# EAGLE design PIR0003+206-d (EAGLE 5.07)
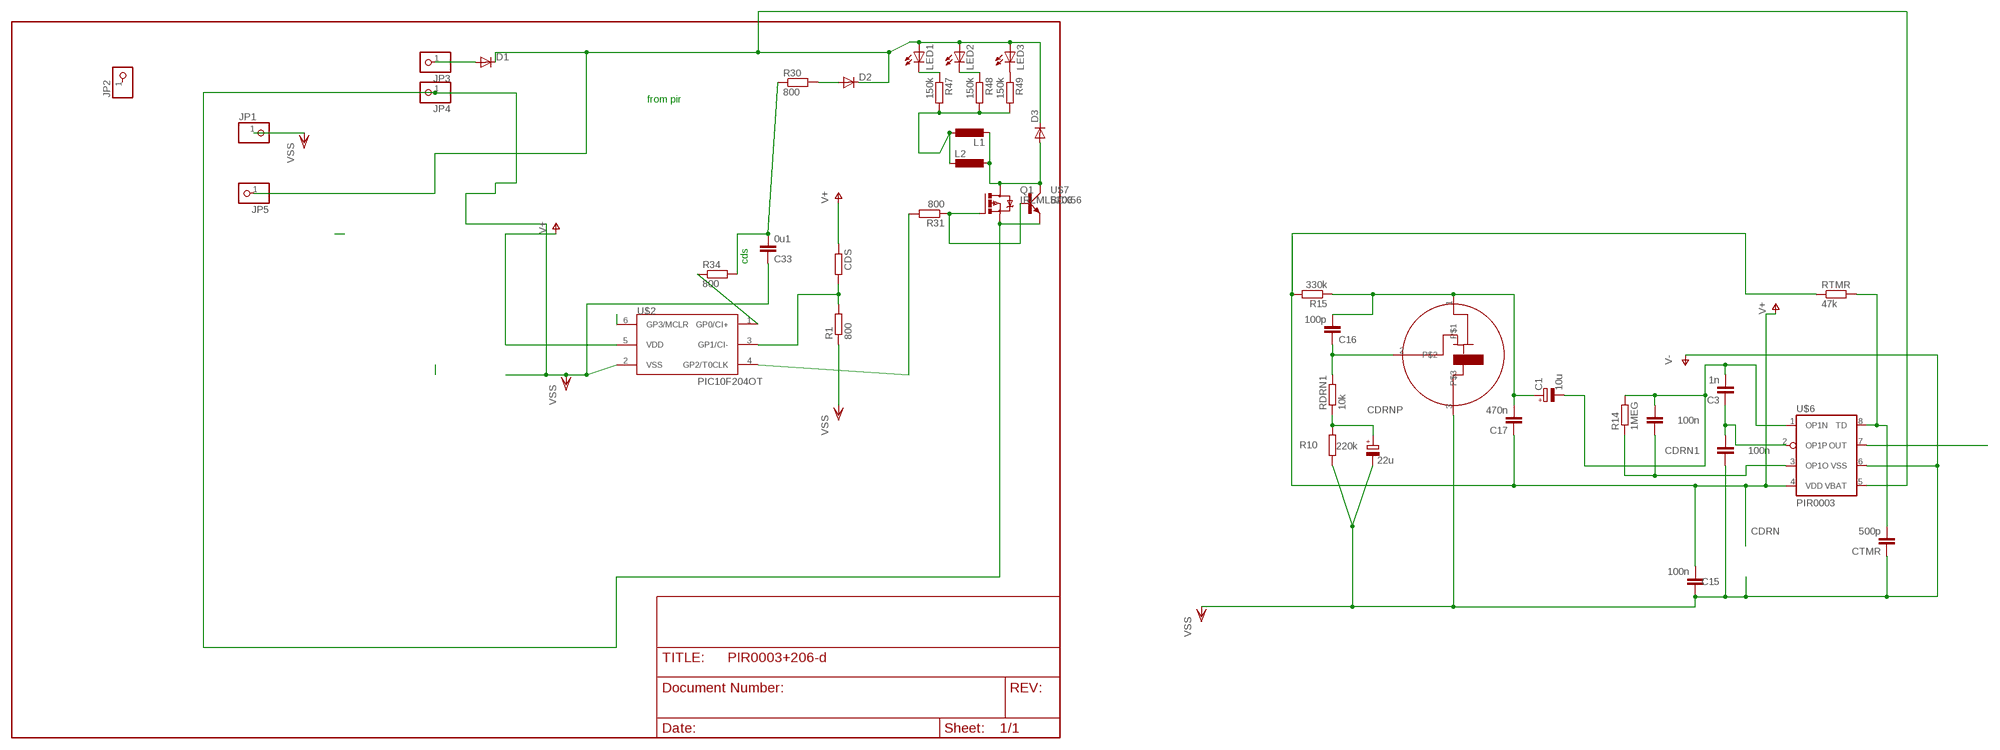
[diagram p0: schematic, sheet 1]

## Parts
C1  10u  CPOL-EUSMCA  [SMC_A]
C3  1n  C-EUC0805  [C0805]
C15  100n  C-EUC1206  [C1206]
C16  100p  C-EUC0805  [C0805]
C17  470n  C-EUC0805  [C0805]
C33  0u1  C-EUC0805  [C0805]
CDRN  100n  C-EUC0805  [C0805]
CDRN1  100n  C-EUC0805  [C0805]
CDRNP  22u  CPOL-EUSMCB  [SMC_B]
CDS  R-EU_0207/5V  [0207/5V]
CTMR  500p  C-EUC0805  [C0805]
D1  DIODE-MINIMELF  [MINIMELF]
D2  DIODE-MINIMELF  [MINIMELF]
D3  DIODE-SMC  [SMC]
JP1  PINHD-1X1  [1X01]
JP2  PINHD-1X1  [1X01]
JP3  PINHD-1X1  [1X01]
JP4  PINHD-1X1  [1X01]
JP5  PINHD-1X1  [1X01]
L1  L-EUL5650M  [L5650M]
L2  L-EU0207/7  [0207/7@1]
LED1  LED1W1MM6  [1W1MM6]
LED2  LED1W1MM6  [1W1MM6]
LED3  LED1W1MM6  [1W1MM6]
PIR1  RE200B  [R200B]
Q1  IRLML5203  [MICRO3]
R1  800  R-EU_R0805  [R0805]
R10  220k  R-EU_R0805  [R0805]
R14  1MEG  R-EU_R0805  [R0805]
R15  330k  R-EU_R0805  [R0805]
R30  800  R-EU_R1206  [R1206]
R31  800  R-EU_R0805  [R0805]
R34  800  R-EU_R1206  [R1206]
R47  150k  R-EU_R1206  [R1206]
R48  150k  R-EU_R1206  [R1206]
R49  150k  R-EU_R1206  [R1206]
RDRN1  10k  R-EU_R0805  [R0805]
RTMR  47k  R-EU_R0805  [R0805]
U$2  PIC10F204OT  [SOT23-6]
U$6  PIR0003  [SO08]
U$7  BCX56  [SOT223]

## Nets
LED-: L1.1 L2.2 R47.2 R48.2 R49.2
N$1: CDS.2 R1.2 U$2.3(GP1/CI-)
N$6: D2.A R30.2
N$8: C1.+ C16.2 C17.2 PIR1.1 R15.1
N$9: CDRNP.+ R10.2 RDRN1.1
N$10: Q1.1(G) R31.1 U$7.1(B)
N$11: D1.A JP3.1
N$14: R31.2 U$2.4(GP2/T0CLK)
N$15: C1.- C3.2 CDRN1.2 R14.2 U$6.1(OP1N)
N$17: C33.2 R30.1 R34.2
N$18: C3.1 CDRN.2 U$6.2(OP1P)
N$20: CDRN1.1 R14.1 U$6.3(OP1O)
N$21: CTMR.2 RTMR.2 U$6.8(TD)
N$23: C16.1 PIR1.2 RDRN1.2
N$26: D3.A L1.2 L2.1 Q1.3(D) U$7.2(C)
N$29: R34.1 U$2.1(GP0/CI+)
N$38: LED1.C R47.1
N$54: LED2.C R48.1
N$55: LED3.C R49.1
OUT: U$2.6(GP3/MCLR) U$6.7(OUT)
V5: D1.C D2.C D3.C JP5.1 LED1.A LED2.A LED3.A U$6.5(VBAT)
V+: C15.2 C17.1 CDS.1 R15.2 RTMR.1 U$2.5(VDD) U$6.4(VDD)
VSS: C15.1 C33.1 CDRN.1 CDRNP.- CTMR.1 JP1.1 JP4.1 PIR1.3 Q1.2(S) R1.1 R10.1 U$2.2(VSS) U$6.6(VSS) U$7.3(E) ; supply symbol labelled V-
Unconnected: JP2.1

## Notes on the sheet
- from pir
- cds

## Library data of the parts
C1 CDRNP = rcl:CPOL-EU: POLARIZED CAPACITOR, European symbol
C3 C15-C17 C33 CDRN CDRN1 CTMR = rcl:C-EU: CAPACITOR, European symbol
CDS = rcl(2):R-EU_: RESISTOR, European symbol
D1-D3 = diode:DIODE-: DIODE
JP1-JP5 = pinhead:PINHD-1X1: PIN HEADER
L1 = rcl-2:L-EU: INDUCTOR, European symbol
L2 = rcl:L-EU: INDUCTOR, European symbol
LED1-LED3 = led:LED: LED
PIR1 = photo-elements:RE200B
Q1 = transistor-power:IRLML5203: HEXFET P-Channel Power MOSFET
R1 R10 R14 R15 R30 R31 R34 R47-R49 RDRN1 RTMR = rcl:R-EU_: RESISTOR, European symbol
U$2 = microchip-3:PIC10F2*: uPC nW 0,25/0,5k Program Flash memory Comparator
U$6 = linear:PIR0003
U$7 = transistor-power:BCX56

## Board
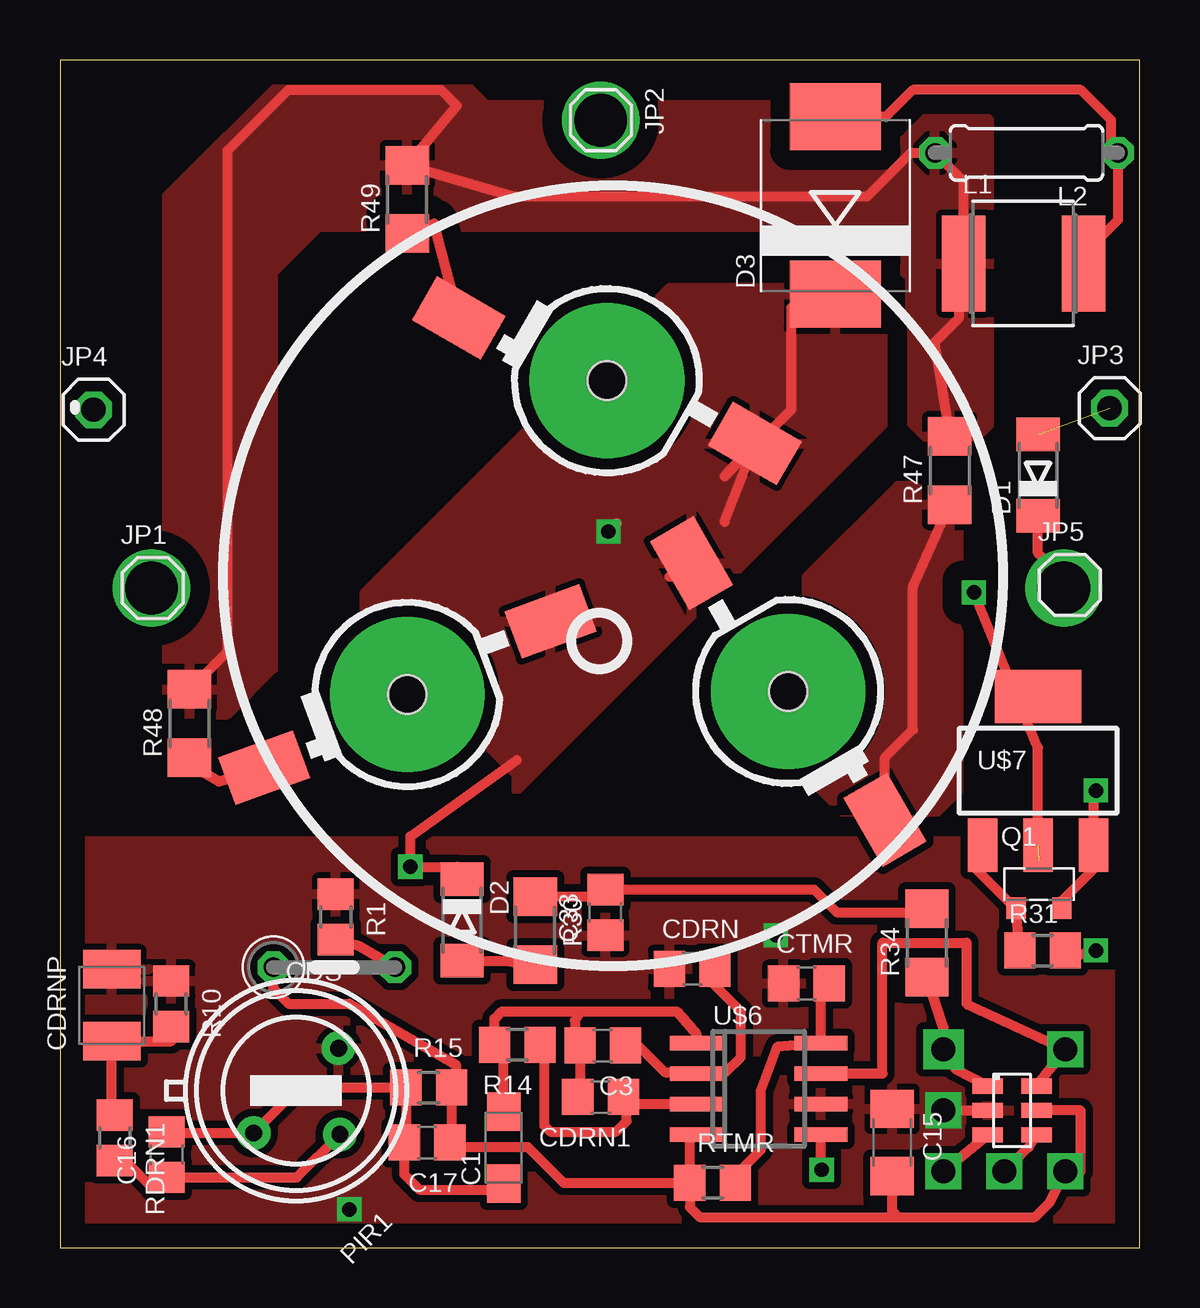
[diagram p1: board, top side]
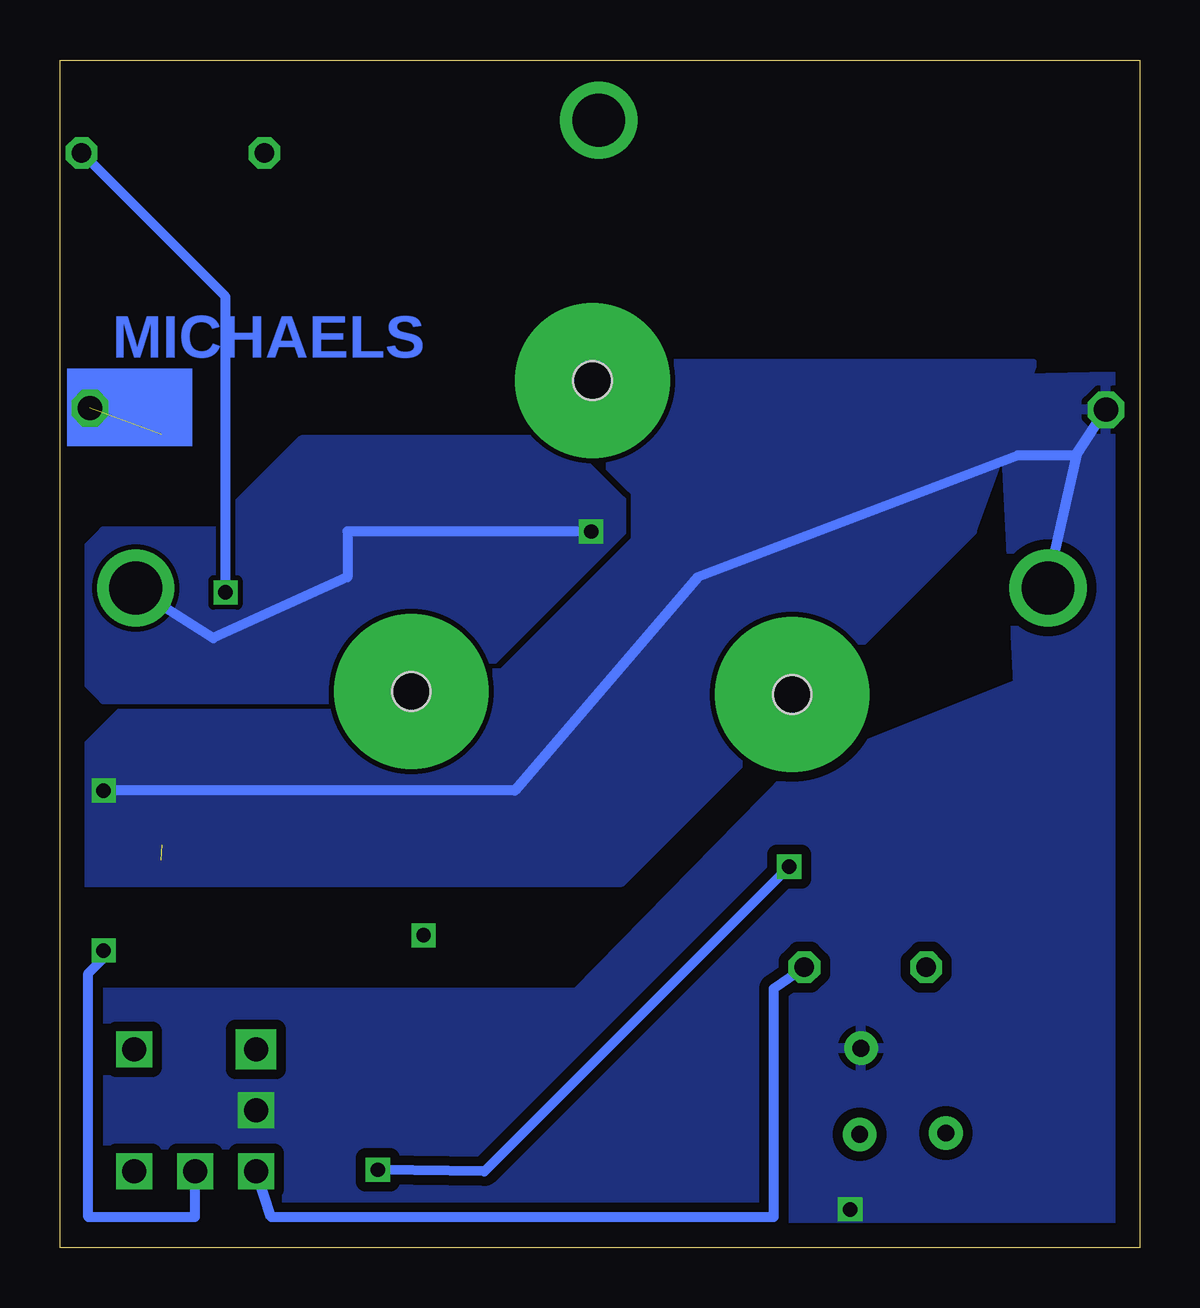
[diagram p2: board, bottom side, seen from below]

Size 45 x 49.5 mm. Coordinates in mm from the lower left corner, seen from the top.
Outline: 0,0 45,0 45,49.5 0,49.5 0,0
Copper layers (1*16): Top 0.035mm / dielectric 1.5mm / Bottom 0.035mm
Design rules "default": minimum track width 10mil, minimum drill 24mil, track to track 8mil, track to pad 8mil, pad to pad 8mil, via to via 8mil, smd to smd 8mil, copper to edge 40mil, drill to drill 8mil, minimum pad ring 10mil, minimum via ring 8mil, stop-mask expansion 4mil, vias tented up to drill 0mil, thermal gap 10mil

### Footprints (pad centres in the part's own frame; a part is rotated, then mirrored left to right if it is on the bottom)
SMC_A = smd 1.6 x 1.4: + -1.5,0; - 1.5,0
C0805 = smd 1.3 x 1.5: 1 -0.95,0; 2 0.95,0
C1206 = smd 1.6 x 1.8: 1 -1.4,0; 2 1.4,0
SMC_B = smd 1.6 x 2.4: + -1.5,0; - 1.5,0
0207/5V = drill 0.813 octagon: 1 -2.54,0; 2 2.54,0
MINIMELF = smd 1.4 x 1.8: A 1.7,0; C -1.7,0
SMC = smd 2.8 x 3.8: A 3.7,0; C -3.7,0
1X01 = drill 1.016 octagon: 1 0,0
L5650M = smd 1.8 x 4: 1 -2.5,0; 2 2.5,0
0207/7@1 = drill 0.813 octagon: 1 -3.81,0; 2 3.81,0
1W1MM6 = smd 3.3 x 2.1: A -6.65,-0.82; C 6.65,0.82 | drill 1.6 pad 6.452 round: P$1 0,0 | hole 1.6: 0,0
R200B = drill 0.7 pad 1.4 round: 1 -2.5,0; 2 0,-2.58; 3 2.5,0
MICRO3 = smd 0.8 x 0.9: 1 -0.95,-1; 2 0.95,-1; 3 0,1
R0805 = smd 1.3 x 1.5: 1 -0.95,0; 2 0.95,0
R1206 = smd 1.6 x 1.803: 1 -1.422,0; 2 1.422,0
SOT23-6 = smd 0.635 x 1.27: 1 -1.016,-1.016; 2 0,-1.016; 3 1.016,-1.016; 4 1.016,1.016; 5 0,1.016; 6 -1.016,1.016
SO08 = smd 0.6 x 2.2: 1 -1.905,-2.6; 2 -0.635,-2.6; 3 0.635,-2.6; 4 1.905,-2.6; 5 1.905,2.6; 6 0.635,2.6; 7 -0.635,2.6; 8 -1.905,2.6
SOT223 = smd 1.219 x 2.235: 1 -2.311,-3.099; 2 0,-3.099; 3 2.311,-3.099 | smd 3.6 x 2.2: 4 0,3.099

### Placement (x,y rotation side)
C1  18.5,4.17 90 top
C3  22.62,8.42 180 top
C15  34.69,4.38 270 top
C16  4.45,3.87 90 top
C17  15.3,4.38 180 top
C33  22.73,13.97 90 top
CDRN  26.35,11.62 0 top
CDRN1  22.54,6.28 180 top
CDRNP  2.16,10.1 90 top
CDS  11.43,11.68 0 top
CTMR  31.11,11.01 0 top
D1  40.77,32.19 90 top
D2  16.76,13.65 270 top
D3  32.32,43.43 90 top
JP1  3.87,27.5 0 top
JP2  22.54,46.99 270 top
JP3  43.75,34.99 0 top
JP4  1.4,34.92 0 top
JP5  42.1,27.62 0 top
L1  40.17,41.01 0 top
L2  40.29,45.63 180 top
LED1  30.35,23.18 300 top
LED2  14.48,23.05 200 top
LED3  22.8,36.13 150 top
PIR1  9.84,6.54 45 top
Q1  40.81,15.14 0 top
R1  11.49,13.78 270 top
R10  4.64,10.16 270 top
R14  19.06,8.46 180 top
R15  15.37,6.67 0 top
R30  19.81,13.21 270 top
R31  40.96,12.38 0 top
R34  36.13,12.7 90 top
R47  37.08,32.38 90 top
R48  5.4,21.84 90 top
R49  14.48,43.69 90 top
RDRN1  2.29,4.57 270 top
RTMR  27.2,2.71 0 top
U$2  39.69,5.71 270 top
U$6  29.12,6.62 270 top
U$7  40.77,19.88 0 top

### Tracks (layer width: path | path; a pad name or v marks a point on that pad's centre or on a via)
LED-
  Top 0.406: R48.2 6.99,24.85 6.99,45.72 9.53,48.26 15.88,48.26 16.54,47.6 R49.2 18.88,43.81 33.66,43.81 35.47,45.63 L2.2 37.67,44.44 L1.1 37.47,40.81 37.47,38.73 36.45,37.72 R47.2
  pour Top (isolate 0.813, rank 2): 38.73,42.55 38.73,46.99 38.1,47.62 17.78,47.62 16.51,48.9 9.53,48.9 4.45,43.81 4.45,22.86 5.08,22.23 6.99,22.23 8.89,24.13 8.89,40.64 10.79,42.55 32.38,42.55 34.92,40.01 34.92,34.92 36.2,33.66 38.1,33.66 38.73,34.29
N$1  (via drill 1)
  Top 0.406: v36.83,3.17 U$2.3 | R1.2 12.45,12.57 CDS.2
  Bottom 0.406: v36.83,3.17 36.2,1.27 15.24,1.27 15.24,10.79 CDS.2
N$2  (via drill 2.2)
  other vias: 3.81,27.5
N$3  (via drill 2.2)
  other vias: 41.85,27.5
N$5  (via drill 2.2)
  other vias: 22.54,46.99
N$6
  Top 0.406: D2.A 18.54,11.95 R30.2
N$8
  Top 0.406: C1.+ 18.24,2.41 14.99,2.41 14.35,3.05 C17.2 14.42,4.45 R15.1 9.97,6.67 PIR1.1 4.5,4.77 C16.2
N$9
  Top 0.406: RDRN1.1 2.16,5.52 CDRNP.+ 4.64,8.6 R10.2
N$10
  Top 0.406: R31.1 Q1.1 39.83,14.14 38.1,15.88 38.1,16.42 U$7.1
N$11  (1 unrouted)
N$14  (via drill 0.6, 1)
  Top 0.406: U$2.4 40.39,4.19 v39.37,3.17 | R31.2 42.44,12.17 v43.18,12.38
  Bottom 0.406: v43.18,12.38 43.18,12.06 43.81,11.43 43.81,1.27 39.37,1.27 v39.37,3.17
N$15
  Top 0.406: 26.67,8.64 26.56,8.52 U$6.1 26.52,8.91 25.72,9.84 21.72,9.84 | 21.72,9.84 21.46,9.46 21.46,8.63 C3.2 21.67,6.9 21.72,6.86 21.72,6.41 CDRN1.2 | 21.72,9.84 18.41,9.84 18.11,9.54 R14.2 18.5,8.46 C1.-
N$17
  Top 0.406: R30.1 22.31,14.63 C33.2 31.43,14.92 32.38,13.97 35.98,13.97 R34.2
N$18
  Top 0.406: CDRN.2 27.24,10.99 28.38,9.84 28.38,7.94 27.75,7.3 26.57,7.3 U$6.2 26.47,7.3 25.21,7.3 24.09,8.42 C3.1
N$20
  Top 0.406: R14.1 20.12,8.46 20.19,8.38 20.19,5.08 20.45,4.83 23.18,4.83 23.62,5.27 23.62,6.14 CDRN1.1 23.78,5.98 U$6.3
N$21
  Top 0.406: RTMR.2 28.15,3.01 29.21,4.06 29.21,6.54 29.91,8.38 31.42,8.51 U$6.8 31.72,10.57 CTMR.2
N$23
  Top 0.406: RDRN1.2 2.73,3.62 3.81,2.54 4.06,2.54 C16.1 9.87,2.92 PIR1.2
N$26  (via drill 0.6)  (1 unrouted)
  Top 0.406: D3.A 34.43,47.13 35.56,48.26 42.55,48.26 43.81,46.99 43.81,45.72 44.01,45.72 L2.1 44.1,42.83 42.55,41.27 42.55,40.89 | 42.55,40.89 42.55,40.64 | 42.55,40.89 L1.2 | U$7.2 40.77,20.83 v38.1,27.3
  Bottom 0.406: v38.1,27.3 38.1,39.63 L2.1
N$29  (via drill 1 pad 1.68)
  Top 0.406: U$2.1 37.34,7.43 v36.83,8.26 36.83,9.18 R34.1
N$38
  Top 0.406: LED1.C 34.39,20.42 35.56,21.59 35.56,27.53 R47.1
  pour Top (isolate 0.813, rank 3): 35.56,31.75 34.92,31.75 31.11,27.94 31.11,19.68 33.02,17.78 36.2,17.78 37.47,19.05 37.47,30.48 36.83,31.11
N$54
  Top 0.406: LED2.C 6.62,19.42 5.08,20.32 5.29,20.32 R48.1
N$55
  Top 0.406: R49.1 15.6,42.68 LED3.C
OUT  (via drill 1)
  Top 0.406: U$2.6 v41.91,8.26 37.78,10.16 37.78,12.7 34.29,12.7 34.29,7.25 U$6.7
V5  (via drill 0.6)
  Top 0.406: U$6.5 31.72,3.2 v31.75,3.24 | D2.C 16.56,15.88 v14.61,15.88 14.61,17.14 19.05,20.32 | 25.4,27.95 25.74,27.95 LED1.A 26.32,30.18 | D3.C 30.48,39.16 30.48,34.92 27.7,32.14 LED3.A 27.7,30.25 | D1.C 40.77,28.96 JP5.1 | v22.86,29.84 23.2,30.18
  Bottom 0.406: v31.75,3.24 27.3,3.17 v14.61,15.88 | v22.86,29.84 33.02,29.84 33.02,27.94 38.61,25.4 JP5.1
  pour Bottom: 42.55,29.84 43.18,29.84 44.45,28.57 44.45,24.13 43.18,22.86 28.57,22.86 21.59,29.84 21.59,31.11 24.13,33.66 34.92,33.66 38.73,29.84
  pour Top (isolate 0.61): 29.84,40.01 33.66,40.01 34.29,39.37 34.29,34.29 19.05,19.05 19.05,19.68 12.7,26.04 12.7,27.3 25.4,40.01
V+  (via drill 1)
  Top 0.406: RTMR.1 20.98,2.71 19.49,4.19 16.44,4.19 C17.1 16.32,4.45 R15.2 16.51,6.86 16.51,7.62 12.06,10.16 9.53,10.16 8.89,10.79 CDS.1 | RTMR.1 26.25,4.45 U$6.4 | U$2.5 42.55,5.71 42.55,3.17 v41.91,3.17 41.27,1.91 40.64,1.27 34.92,1.27 | C15.2 34.69,1.51 34.92,1.27 | RTMR.1 26.25,1.69 26.67,1.27 34.92,1.27
VSS  (via drill 0.6, 1)
  Top 0.406: v36.83,5.71 U$2.2 | v43.18,19.05 43.08,18.95 U$7.3 43.18,16.67 43.18,15.88 41.76,14.45 Q1.2
  Bottom 0.406: v43.18,19.05 26.04,19.05 18.41,27.94 5.08,33.02 2.67,33.02 JP4.1 2.6,33.08 JP1.1
  other vias: 29.84,13.02 12.06,1.59
  pour Top (isolate 0.305): 0.25,16.95 39.69,16.95 41.59,11.75 43.81,11.75 43.81,8.89 44.26,1.21 0.38,1.21 0.38,1.65
  pour Bottom (isolate 0.406): 0.25,36.32 5.71,36.2 5.08,23.5 14.61,19.68 23.5,10.6 44.26,10.6 44.26,1.21 0.38,1.21 0.38,1.65
  pour Bottom (rank 5): 4.45,36.83 27.94,36.83 44.45,20.32 44.45,15.24 21.59,15.24 6.99,29.84
(copper drawn outside any net)
  shapes: Bottom area x1

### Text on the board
Bottom: MICHAELS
